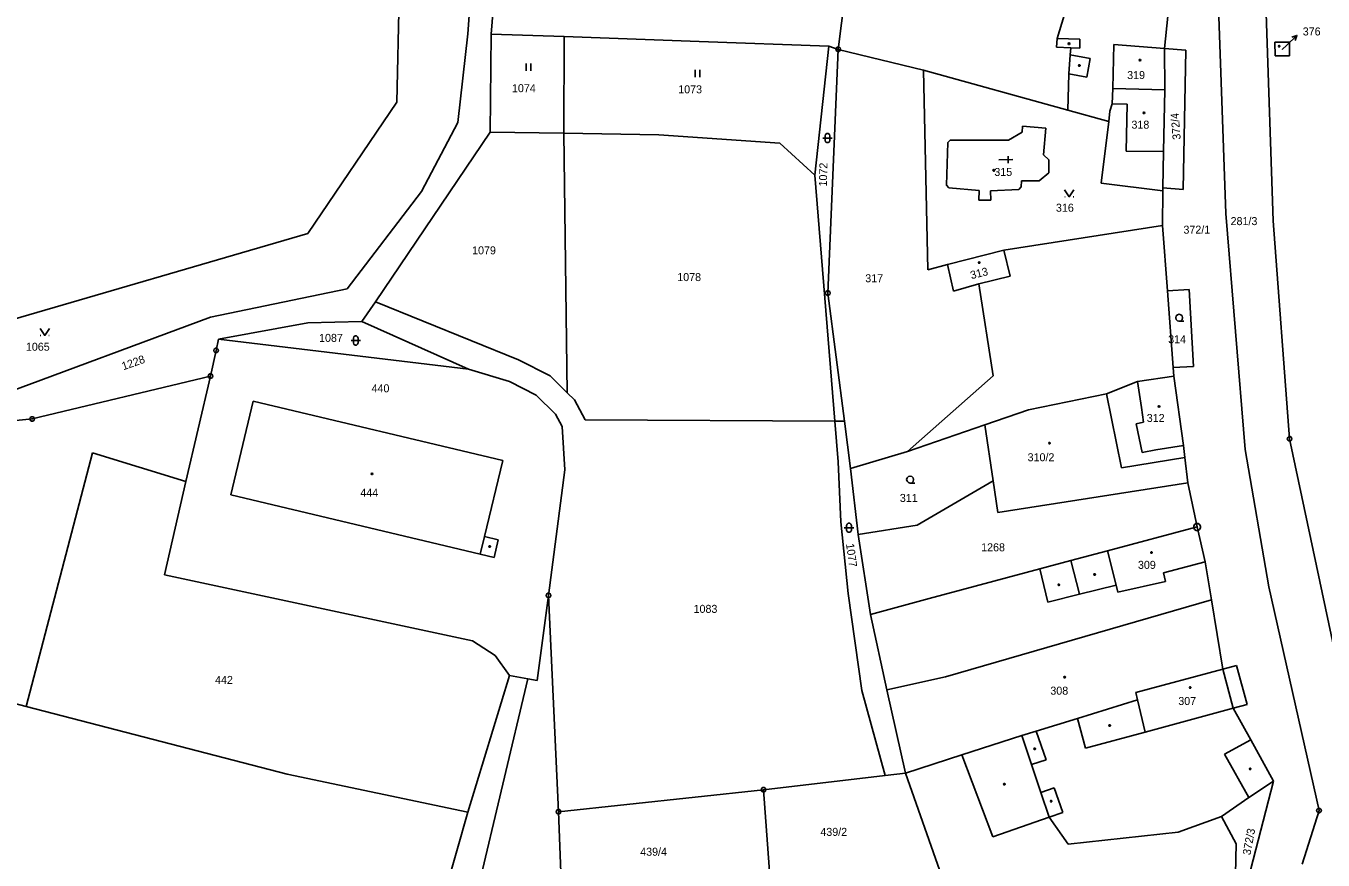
# Model space of a CAD drawing. Extents: x -812394 to -807601, y -1013098 to -1009266.
# Drawn here: x -811273.1 to -810997.6, y -1011589.1 to -1011411.9 of the extents above; entities that cross this region are included whole.
import ezdxf

# ---------------------------------------------------------------- set-up
doc = ezdxf.new("R2010")
doc.units = 0
for name, color, linetype in [('KN_HRANICE', 7, 'Continuous'), ('KN_KULTURY', 7, 'Continuous'), ('KN_MEZNIKY', 7, 'Continuous'), ('KN_PARCELY', 7, 'Continuous'), ('KN_SLUCKY', 7, 'Continuous')]:
    doc.layers.add(name, color=color, linetype=linetype)

# ---------------------------------------------------------------- blocks, each defined once
blk = doc.blocks.new('101')
blk.add_line((-0.05, 0), (0.05, 0))
blk.add_lwpolyline([(0.19, 0.72), (0.53, 0.53), (0.72, 0.19), (0.72, -0.2), (0.53, -0.54), (0.19, -0.73), (-0.2, -0.73), (-0.54, -0.54), (-0.73, -0.2), (-0.73, 0.19), (-0.54, 0.53), (-0.2, 0.72), (0.19, 0.72)])
blk = doc.blocks.new('304')
blk.add_lwpolyline([(0, 0), (-0.38, 0.1), (-0.65, 0.37), (-0.75, 0.74), (-0.65, 1.11), (-0.38, 1.38), (-0.01, 1.48), (0.36, 1.38), (0.63, 1.11), (0.73, 0.73), (0.63, 0.35), (0.36, 0.08), (-0.02, -0.02), (0.98, -0.02)])
blk = doc.blocks.new('306')
for p, q in [((-0.5, 1.5), (-0.5, 0)), ((0.5, 0), (0.5, 1.5))]:
    blk.add_line(p, q)
blk = doc.blocks.new('314')
for p, q in [((-0.95, 0), (-0.85, 0)), ((0.85, 0), (0.95, 0))]:
    blk.add_line(p, q)
blk.add_lwpolyline([(-1, 1.5), (0, 0), (1, 1.5)])
blk = doc.blocks.new('316')
for points in [[(-1, 1), (0.27, 1), (1, 1)], [(-0.5, 1.5), (-0.4, 1.79), (-0.15, 1.97), (0.16, 1.97), (0.41, 1.79), (0.51, 1.5), (0.51, 0.5), (0.41, 0.21), (0.16, 0.03), (-0.15, 0.03), (-0.4, 0.21), (-0.5, 0.5), (-0.5, 1.5)]]:
    blk.add_lwpolyline(points)
blk = doc.blocks.new('NAHRADNI_SYMBOL')
blk.add_lwpolyline([(0.09, 0.15), (0.18, 0), (0.09, -0.15), (-0.09, -0.15), (-0.18, 0), (-0.09, 0.15), (0.09, 0.15)])
blk = doc.blocks.new('10292')
blk.add_line((0, 3), (0, 0))
blk.add_lwpolyline([(-0.5, 2), (0, 3), (0.5, 2)])
blk = doc.blocks.new('402')
blk.add_lwpolyline([(0.09, 0.15), (0.18, 0), (0.09, -0.15), (-0.09, -0.15), (-0.18, 0), (-0.09, 0.15), (0.09, 0.15)])
blk = doc.blocks.new('4091')
for p, q in [((0, 0), (0, 3)), ((0.75, 2), (-0.75, 2))]:
    blk.add_line(p, q)
blk = doc.blocks.new('105')
blk.add_line((-0.12, 0), (0.12, 0))
blk.add_lwpolyline([(0.15, 0.48), (0.4, 0.3), (0.5, 0.01), (0.4, -0.28), (0.15, -0.46), (-0.16, -0.46), (-0.41, -0.28), (-0.51, 0.01), (-0.41, 0.3), (-0.16, 0.48), (0.15, 0.48)])

msp = doc.modelspace()

# ---------------------------------------------------------------- linework, layer by layer
at = {"layer": 'KN_HRANICE'}
for p, q in [((-811194.35, -1011428.07), (-811191.38, -1011303.47)), ((-811172.89, -1011326.55), (-811179.25, -1011413.51)), ((-811174.26, -1011413.61), (-811170.58, -1011363.44)), ((-811096.21, -1011383.14), (-811100.57, -1011416.83)), ((-811054.01, -1011414.53), (-811051.11, -1011404.88)), ((-811031.22, -1011416.63), (-811030.55, -1011409.8)), ((-811018.24, -1011451.73), (-811019.73, -1011409.84)), ((-811008.13, -1011453.24), (-811009.67, -1011409.19)), ((-811179.25, -1011413.51), (-811181.37, -1011432.37)), ((-811174.5, -1011434.42), (-811174.26, -1011413.61)), ((-811174.26, -1011413.61), (-811158.74, -1011414.11)), ((-811158.74, -1011414.11), (-811158.86, -1011434.66)), ((-811130.11, -1011415.14), (-811158.74, -1011414.11)), ((-811102.55, -1011416.12), (-811130.11, -1011415.14)), ((-811054.16, -1011416.37), (-811054.01, -1011414.53)), ((-811007.8, -1011415.34), (-811004.69, -1011415.34)), ((-811007.76, -1011418.21), (-811007.8, -1011415.34)), ((-811004.69, -1011415.34), (-811004.69, -1011418.19)), ((-811105.53, -1011443.55), (-811102.55, -1011416.12)), ((-811100.57, -1011416.83), (-811102.76, -1011468.61)), ((-811100.57, -1011416.83), (-811102.55, -1011416.12)), ((-811100.57, -1011416.83), (-811082.43, -1011421.27)), ((-811051.17, -1011416.5), (-811054.16, -1011416.37)), ((-811051.58, -1011422.05), (-811051.28, -1011418.03)), ((-811051.28, -1011418.03), (-811051.17, -1011416.5)), ((-811042.21, -1011425.17), (-811042.03, -1011415.82)), ((-811042.03, -1011415.82), (-811031.22, -1011416.63)), ((-811026.7, -1011416.99), (-811031.22, -1011416.63)), ((-811031.22, -1011416.63), (-811031.17, -1011425.43)), ((-811027.28, -1011446.6), (-811026.7, -1011416.99)), ((-811004.69, -1011418.19), (-811007.76, -1011418.21)), ((-811082.43, -1011421.27), (-811081.48, -1011463.7)), ((-811082.43, -1011421.27), (-811051.74, -1011429.77)), ((-811051.74, -1011429.77), (-811051.58, -1011422.05)), ((-811042.36, -1011428.43), (-811042.21, -1011425.17)), ((-811042.21, -1011425.17), (-811031.17, -1011425.43)), ((-811031.17, -1011425.43), (-811031.47, -1011438.51)), ((-811213.2, -1011455.92), (-811194.35, -1011428.07)), ((-811042.83, -1011429.97), (-811042.36, -1011428.43)), ((-811051.74, -1011429.77), (-811043.09, -1011432.16)), ((-811043.09, -1011432.16), (-811042.83, -1011429.97)), ((-811198.88, -1011470.45), (-811174.5, -1011434.42)), ((-811181.37, -1011432.37), (-811189.07, -1011447.02)), ((-811174.5, -1011434.42), (-811158.86, -1011434.66)), ((-811158.86, -1011434.66), (-811158.14, -1011489.78)), ((-811064.35, -1011436.14), (-811061.46, -1011434.46)), ((-811061.46, -1011434.46), (-811061.38, -1011433.17)), ((-811061.38, -1011433.17), (-811056.43, -1011433.57)), ((-811056.43, -1011433.57), (-811056.94, -1011439.23)), ((-811044.66, -1011445.25), (-811043.09, -1011432.16)), ((-811077.55, -1011445.67), (-811077.3, -1011436.6)), ((-811077.3, -1011436.6), (-811076.77, -1011436.14)), ((-811076.77, -1011436.14), (-811064.35, -1011436.14)), ((-811056.94, -1011439.23), (-811055.82, -1011440.32)), ((-811031.47, -1011438.51), (-811031.57, -1011446.26)), ((-811055.82, -1011440.32), (-811055.82, -1011443.07)), ((-811101.25, -1011495.79), (-811105.53, -1011443.55)), ((-811077.04, -1011446.24), (-811077.55, -1011445.67)), ((-811061.64, -1011444.79), (-811061.68, -1011446.05)), ((-811057.83, -1011444.74), (-811061.64, -1011444.79)), ((-811055.82, -1011443.07), (-811057.83, -1011444.74)), ((-811031.58, -1011446.91), (-811044.66, -1011445.25)), ((-811189.07, -1011447.02), (-811204.87, -1011467.74)), ((-811070.62, -1011446.79), (-811077.04, -1011446.24)), ((-811070.65, -1011448.85), (-811070.62, -1011446.79)), ((-811062.21, -1011446.58), (-811068.18, -1011446.87)), ((-811068.18, -1011446.87), (-811068.16, -1011448.89)), ((-811061.68, -1011446.05), (-811062.21, -1011446.58)), ((-811031.68, -1011454.25), (-811031.58, -1011446.91)), ((-811031.58, -1011446.91), (-811031.57, -1011446.26)), ((-811031.57, -1011446.26), (-811027.28, -1011446.6)), ((-811068.16, -1011448.89), (-811070.65, -1011448.85)), ((-811014.13, -1011501.83), (-811018.24, -1011451.73)), ((-811004.66, -1011499.57), (-811008.13, -1011453.24)), ((-811303.93, -1011482.35), (-811213.2, -1011455.92)), ((-811065.4, -1011459.51), (-811031.68, -1011454.25)), ((-811030.62, -1011468.1), (-811031.68, -1011454.25)), ((-811077.31, -1011462.56), (-811065.4, -1011459.51)), ((-811081.48, -1011463.7), (-811077.31, -1011462.56)), ((-811076.05, -1011468.17), (-811077.31, -1011462.56)), ((-811204.87, -1011467.74), (-811233.91, -1011473.74)), ((-811070.65, -1011466.68), (-811076.05, -1011468.17)), ((-811067.64, -1011486.22), (-811070.65, -1011466.68)), ((-811201.72, -1011474.65), (-811198.88, -1011470.45)), ((-811168.48, -1011482.77), (-811198.88, -1011470.45)), ((-811102.76, -1011468.61), (-811099.25, -1011495.85)), ((-811025.99, -1011467.86), (-811030.62, -1011468.1)), ((-811029.37, -1011484.43), (-811030.62, -1011468.1)), ((-811025.07, -1011484.23), (-811025.99, -1011467.86)), ((-811233.91, -1011473.74), (-811289.1, -1011494.23)), ((-811232.17, -1011478.43), (-811213.22, -1011474.91)), ((-811213.22, -1011474.91), (-811201.72, -1011474.65)), ((-811201.72, -1011474.65), (-811179.11, -1011484.8)), ((-811232.17, -1011478.43), (-811232.72, -1011480.8)), ((-811179.11, -1011484.8), (-811232.17, -1011478.43)), ((-811232.72, -1011480.8), (-811233.91, -1011486.25)), ((-811161.78, -1011486.19), (-811168.48, -1011482.77)), ((-811025.07, -1011484.23), (-811029.37, -1011484.43)), ((-811233.91, -1011486.25), (-811271.79, -1011495.36)), ((-811233.91, -1011486.25), (-811239.11, -1011508.63)), ((-811170.35, -1011487.43), (-811179.11, -1011484.8)), ((-811158.14, -1011489.78), (-811161.78, -1011486.19)), ((-811085.84, -1011502.26), (-811067.64, -1011486.22)), ((-811036.96, -1011487.4), (-811029.23, -1011486.26)), ((-811029.37, -1011484.43), (-811029.23, -1011486.26)), ((-811029.23, -1011486.26), (-811027.21, -1011501.02)), ((-811164.74, -1011490.29), (-811170.35, -1011487.43)), ((-811158.14, -1011489.78), (-811156.58, -1011491.32)), ((-811043.53, -1011490.02), (-811036.96, -1011487.4)), ((-811229.57, -1011511.44), (-811224.84, -1011491.55)), ((-811224.84, -1011491.55), (-811171.82, -1011504.19)), ((-811160.62, -1011494.36), (-811164.74, -1011490.29)), ((-811156.58, -1011491.32), (-811154.29, -1011495.54)), ((-811060.1, -1011493.41), (-811043.53, -1011490.02)), ((-811043.53, -1011490.02), (-811040.39, -1011505.73)), ((-811159.21, -1011496.95), (-811160.62, -1011494.36)), ((-811069.41, -1011496.61), (-811060.1, -1011493.41)), ((-811271.79, -1011495.36), (-811280.14, -1011496.2)), ((-811158.66, -1011506.17), (-811159.21, -1011496.95)), ((-811154.29, -1011495.54), (-811101.25, -1011495.79)), ((-811099.25, -1011495.85), (-811101.25, -1011495.79)), ((-811101.25, -1011495.79), (-811100.54, -1011504.44)), ((-811099.25, -1011495.85), (-811097.96, -1011505.89)), ((-811085.84, -1011502.26), (-811069.41, -1011496.61)), ((-811067.66, -1011508.49), (-811069.41, -1011496.61)), ((-810988.29, -1011576.92), (-811004.66, -1011499.57)), ((-811258.94, -1011502.58), (-811273.05, -1011556.43)), ((-811239.11, -1011508.63), (-811258.94, -1011502.58)), ((-811097.96, -1011505.89), (-811085.84, -1011502.26)), ((-811040.39, -1011505.73), (-811026.92, -1011503.52)), ((-811026.92, -1011503.52), (-811027.21, -1011501.02)), ((-811026.29, -1011508.89), (-811026.92, -1011503.52)), ((-811009.09, -1011531.03), (-811014.13, -1011501.83)), ((-811171.82, -1011504.19), (-811175.7, -1011520.33)), ((-811162.1, -1011532.85), (-811158.66, -1011506.17)), ((-811100.54, -1011504.44), (-811100.02, -1011517.23)), ((-811097.96, -1011505.89), (-811096.31, -1011519.91)), ((-811239.11, -1011508.63), (-811243.65, -1011528.46)), ((-811083.76, -1011517.9), (-811067.66, -1011508.49)), ((-811066.67, -1011515.22), (-811067.66, -1011508.49)), ((-811026.29, -1011508.89), (-811066.67, -1011515.22)), ((-811024.27, -1011518.27), (-811026.29, -1011508.89)), ((-811176.6, -1011524.08), (-811229.57, -1011511.44)), ((-811100.02, -1011517.23), (-811098.41, -1011532.42)), ((-811096.31, -1011519.91), (-811083.76, -1011517.9)), ((-811096.31, -1011519.91), (-811093.69, -1011536.91)), ((-811043.33, -1011523.37), (-811024.27, -1011518.27)), ((-811022.62, -1011525.72), (-811024.27, -1011518.27)), ((-811172.77, -1011521.02), (-811175.7, -1011520.33)), ((-811173.66, -1011524.78), (-811172.77, -1011521.02)), ((-811176.6, -1011524.08), (-811173.66, -1011524.78)), ((-811057.69, -1011527.22), (-811051.12, -1011525.46)), ((-811051.12, -1011525.46), (-811043.33, -1011523.37)), ((-811081.24, -1011533.53), (-811057.69, -1011527.22)), ((-811021.28, -1011533.77), (-811022.62, -1011525.72)), ((-811243.65, -1011528.46), (-811178.27, -1011542.52)), ((-810998.41, -1011578.57), (-811009.09, -1011531.03)), ((-811164.49, -1011550.91), (-811162.1, -1011532.85)), ((-811159.98, -1011578.81), (-811162.1, -1011532.85)), ((-811098.41, -1011532.42), (-811095.53, -1011553.04)), ((-811081.24, -1011533.53), (-811093.69, -1011536.91)), ((-811077.76, -1011550.14), (-811021.28, -1011533.77)), ((-811018.83, -1011548.49), (-811021.28, -1011533.77)), ((-811093.69, -1011536.91), (-811090.2, -1011552.87)), ((-811178.27, -1011542.52), (-811173.42, -1011545.58)), ((-811173.42, -1011545.58), (-811170.39, -1011549.84)), ((-811301.11, -1011549.16), (-811273.05, -1011556.43)), ((-811179.22, -1011578.9), (-811170.39, -1011549.84)), ((-811170.39, -1011549.84), (-811166.46, -1011550.55)), ((-811090.2, -1011552.87), (-811077.76, -1011550.14)), ((-811037.35, -1011553.47), (-811018.83, -1011548.49)), ((-811018.83, -1011548.49), (-811015.93, -1011547.71)), ((-811015.93, -1011547.71), (-811013.7, -1011556.01)), ((-811178.18, -1011599.83), (-811166.46, -1011550.55)), ((-811166.46, -1011550.55), (-811164.49, -1011550.91)), ((-811095.53, -1011553.04), (-811090.56, -1011571.12)), ((-811090.2, -1011552.87), (-811086.24, -1011570.61)), ((-811049.73, -1011558.97), (-811036.98, -1011555.03)), ((-811036.98, -1011555.03), (-811037.35, -1011553.47)), ((-811273.05, -1011556.43), (-811217.62, -1011570.79)), ((-811013.7, -1011556.01), (-811016.66, -1011556.83)), ((-811012.91, -1011563.56), (-811016.66, -1011556.83)), ((-811058.48, -1011561.67), (-811049.73, -1011558.97)), ((-811074.28, -1011566.74), (-811061.54, -1011562.61)), ((-811061.54, -1011562.61), (-811058.48, -1011561.67)), ((-811008.1, -1011572.3), (-811012.91, -1011563.56)), ((-811086.24, -1011570.61), (-811074.28, -1011566.74)), ((-811074.28, -1011566.74), (-811067.73, -1011584.15)), ((-811217.62, -1011570.79), (-811179.22, -1011578.9)), ((-811090.56, -1011571.12), (-811116.42, -1011574.14)), ((-811086.24, -1011570.61), (-811090.56, -1011571.12)), ((-811078.55, -1011592.58), (-811086.24, -1011570.61)), ((-811008.1, -1011572.3), (-811015.03, -1011599.04)), ((-811008.1, -1011572.3), (-811013.29, -1011575.78)), ((-811116.42, -1011574.14), (-811159.98, -1011578.81)), ((-811114.74, -1011597.01), (-811116.42, -1011574.14)), ((-811013.29, -1011575.78), (-811019.13, -1011579.83)), ((-811186.53, -1011604.51), (-811179.22, -1011578.9)), ((-811159.98, -1011578.81), (-811159.05, -1011601.95)), ((-811067.73, -1011584.15), (-811055.76, -1011579.97)), ((-811055.76, -1011579.97), (-811051.71, -1011585.72)), ((-811028.3, -1011583.16), (-811019.13, -1011579.83)), ((-811019.13, -1011579.83), (-811016.02, -1011585.65)), ((-811001.99, -1011589.96), (-810998.41, -1011578.57)), ((-811051.71, -1011585.72), (-811028.3, -1011583.16)), ((-811016.02, -1011585.65), (-811016.27, -1011596.11))]:
    msp.add_line(p, q, dxfattribs=at)
msp.add_lwpolyline([(-811158.86, -1011434.66), (-811138.69, -1011434.98), (-811112.99, -1011436.74), (-811105.53, -1011443.55)], dxfattribs=at)
at = {"layer": 'KN_PARCELY'}
msp.add_line((-811006.23, -1011416.88), (-811005.27, -1011415.96), dxfattribs=at)
at = {"layer": 'KN_SLUCKY'}
for p, q in [((-811054.01, -1011414.53), (-811049.22, -1011414.7)), ((-811049.22, -1011414.7), (-811049.26, -1011416.58)), ((-811051.28, -1011418.03), (-811047.03, -1011418.74)), ((-811051.17, -1011416.5), (-811049.26, -1011416.58)), ((-811047.71, -1011422.71), (-811047.03, -1011418.74)), ((-811051.58, -1011422.05), (-811047.71, -1011422.71)), ((-811039.18, -1011428.46), (-811042.36, -1011428.43)), ((-811039.38, -1011438.44), (-811039.18, -1011428.46)), ((-811031.47, -1011438.51), (-811039.38, -1011438.44)), ((-811064.03, -1011465.05), (-811065.4, -1011459.51)), ((-811064.03, -1011465.05), (-811070.65, -1011466.68)), ((-811036.15, -1011492.95), (-811036.96, -1011487.4)), ((-811035.7, -1011496.05), (-811036.15, -1011492.95)), ((-811037.28, -1011496.38), (-811035.7, -1011496.05)), ((-811036.01, -1011502.47), (-811037.28, -1011496.38)), ((-811033.05, -1011501.88), (-811036.01, -1011502.47)), ((-811027.21, -1011501.02), (-811033.05, -1011501.88)), ((-811175.7, -1011520.33), (-811176.6, -1011524.08)), ((-811049.33, -1011532.61), (-811051.12, -1011525.46)), ((-811041.5, -1011530.65), (-811043.33, -1011523.37)), ((-811056, -1011534.29), (-811057.69, -1011527.22)), ((-811022.62, -1011525.72), (-811031.45, -1011528.02)), ((-811031.03, -1011529.88), (-811031.45, -1011528.02)), ((-811049.33, -1011532.61), (-811041.5, -1011530.65)), ((-811041.5, -1011530.65), (-811041.13, -1011532.12)), ((-811031.03, -1011529.88), (-811041.13, -1011532.12)), ((-811056, -1011534.29), (-811049.33, -1011532.61)), ((-811018.83, -1011548.49), (-811016.66, -1011556.83)), ((-811036.98, -1011555.03), (-811035.34, -1011561.89)), ((-811016.66, -1011556.83), (-811035.34, -1011561.89)), ((-811048.01, -1011565.32), (-811049.73, -1011558.97)), ((-811059.48, -1011568.8), (-811061.54, -1011562.61)), ((-811058.48, -1011561.67), (-811056.41, -1011567.76)), ((-811035.34, -1011561.89), (-811048.01, -1011565.32)), ((-811012.91, -1011563.56), (-811018.46, -1011566.59)), ((-811018.46, -1011566.59), (-811013.29, -1011575.78)), ((-811056.41, -1011567.76), (-811059.48, -1011568.8)), ((-811057.5, -1011574.74), (-811059.48, -1011568.8)), ((-811054.65, -1011573.74), (-811057.5, -1011574.74)), ((-811055.76, -1011579.97), (-811057.5, -1011574.74)), ((-811052.83, -1011578.95), (-811054.65, -1011573.74)), ((-811055.76, -1011579.97), (-811052.83, -1011578.95))]:
    msp.add_line(p, q, dxfattribs=at)

# ---------------------------------------------------------------- block references
at = {"layer": 'KN_KULTURY'}
for name, p in [('402', (-811051.54, -1011415.62)), ('402', (-811006.87, -1011416.17)), ('306', (-811166.35, -1011421.36)), ('402', (-811049.32, -1011420.27)), ('NAHRADNI_SYMBOL', (-811036.46, -1011419.11)), ('306', (-811130.47, -1011422.71)), ('402', (-811035.61, -1011430.34)), ('316', (-811102.83, -1011436.68)), ('402', (-811067.5, -1011442.54)), ('314', (-811051.48, -1011448.16)), ('402', (-811070.62, -1011462.14)), ('304', (-811028.11, -1011474.58)), ('314', (-811269.11, -1011477.61)), ('316', (-811203.05, -1011479.68)), ('402', (-811032.4, -1011492.69)), ('NAHRADNI_SYMBOL', (-811055.66, -1011500.48)), ('402', (-811199.61, -1011507.03)), ('304', (-811085.27, -1011508.97)), ('316', (-811098.27, -1011519.47)), ('402', (-811174.59, -1011522.46)), ('402', (-811034, -1011523.75)), ('402', (-811046.09, -1011528.39)), ('402', (-811053.7, -1011530.57)), ('NAHRADNI_SYMBOL', (-811052.45, -1011550.21)), ('402', (-811025.77, -1011552.43)), ('402', (-811042.88, -1011560.48)), ('402', (-811058.82, -1011565.41)), ('402', (-811013.04, -1011569.71)), ('402', (-811065.25, -1011572.96)), ('402', (-811055.3, -1011576.55))]:
    msp.add_blockref(name, p, dxfattribs=at)
at = {"layer": 'KN_KULTURY', "rotation": -89.16284999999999}
msp.add_blockref('4091', (-811066.45, -1011440.29), dxfattribs=at)
at = {"layer": 'KN_MEZNIKY'}
for name, p in [('105', (-811100.57, -1011416.83)), ('105', (-811102.76, -1011468.61)), ('105', (-811232.72, -1011480.8)), ('105', (-811233.91, -1011486.25)), ('105', (-811271.79, -1011495.36)), ('105', (-811004.66, -1011499.57)), ('101', (-811024.3, -1011518.29)), ('105', (-811162.1, -1011532.85)), ('105', (-811116.42, -1011574.14)), ('105', (-811159.98, -1011578.81)), ('105', (-810998.41, -1011578.57))]:
    msp.add_blockref(name, p, dxfattribs=at)
at = {"layer": 'KN_PARCELY', "rotation": -46.13372000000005}
msp.add_blockref('10292', (-811005.27, -1011415.96), dxfattribs=at)

# ---------------------------------------------------------------- texts
at = {"layer": 'KN_PARCELY'}
for s, height, p in [('376', 1.7, (-811001.87, -1011413.88)), ('376', 0.1, (-811006.37, -1011416.88)), ('319', 1.7, (-811039.17, -1011423.14)), ('1074', 1.7, (-811169.86, -1011425.93)), ('1073', 1.7, (-811134.54, -1011426.17)), ('318', 1.7, (-811038.26, -1011433.68)), ('315', 1.7, (-811067.39, -1011443.73)), ('316', 1.7, (-811054.3, -1011451.33)), ('281/3', 1.7, (-811017.2, -1011454.17)), ('372/1', 1.7, (-811027.22, -1011455.99)), ('1079', 1.7, (-811178.33, -1011460.38)), ('1078', 1.7, (-811134.75, -1011466.06)), ('317', 1.7, (-811094.81, -1011466.31)), ('1087', 1.7, (-811210.84, -1011478.98)), ('314', 1.7, (-811030.46, -1011479.26)), ('1065', 1.7, (-811273.12, -1011480.86)), ('440', 1.7, (-811199.69, -1011489.69)), ('312', 1.7, (-811035.01, -1011495.99)), ('310/2', 1.7, (-811060.32, -1011504.34)), ('444', 1.7, (-811202.08, -1011511.88)), ('311', 1.7, (-811087.46, -1011512.98)), ('1268', 1.7, (-811070.19, -1011523.47)), ('309', 1.7, (-811036.88, -1011527.2)), ('1083', 1.7, (-811131.28, -1011536.55)), ('442', 1.7, (-811232.94, -1011551.65)), ('308', 1.7, (-811055.49, -1011553.93)), ('307', 1.7, (-811028.31, -1011556.12)), ('439/2', 1.7, (-811104.35, -1011583.93)), ('439/4', 1.7, (-811142.62, -1011588.15))]:
    msp.add_text(s, height=height, dxfattribs=at).set_placement(p)
for s, rotation, p in [('372/4', 94.71, (-811027.79, -1011435.96)), ('1072', 88.465, (-811102.97, -1011445.99)), ('313', 13.923, (-811072.26, -1011465.67)), ('1228', 19.481, (-811252.42, -1011485.03)), ('1077', 277.942, (-811098.9, -1011521.92)), ('372/3', 79.412, (-811013, -1011588.11))]:
    msp.add_text(s, height=1.7, rotation=rotation, dxfattribs=at).set_placement(p)

doc.saveas('drawing.dxf')
